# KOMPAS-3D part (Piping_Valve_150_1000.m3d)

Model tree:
1. Plane XY
2. Plane ZX
3. Plane ZY
4. X Axis
5. Y Axis
6. Z Axis
7. Origin
8. Sketch:1
9. Extrude:1  (labels: На расстояние 1; На расстояние 2)
     Толщина стенки 1 = 1; Толщина стенки 2 = 1; Расстояние 2 = 10
10. Sketch:5
11. Extrude:2  (labels: На расстояние 1; На расстояние 2)
     Толщина стенки 1 = 1; Толщина стенки 2 = 1; Угол 1 = 45; Расстояние 2 = 10
12. Sketch:7
13. Cut-Extrude:2  (labels: На расстояние 1)
     Толщина стенки 1 = 1; Толщина стенки 2 = 1; Расстояние 1 = 10; Расстояние 2 = 11
14. Intersection Axis of Two Planes:1
15. Circular Pattern:1  (labels: Экземпляр ( 1, 2 );; Вырезать элемент выдавливания:2; Экземпляр ( 1, 3 );; Вырезать элемент выдавливания:2)
16. Вырезать элемент выдавливания:2  (labels: Экземпляр ( 1, 6 );; Экземпляр ( 1, 7 );; Экземпляр ( 1, 8 );)
     N 1 = 1; Шаг 1 = 10; Шаг 2 = 360
17. Sketch:6
18. Cut-Extrude:1  (labels: На расстояние 1; На расстояние 2)
     Толщина стенки 1 = 1; Толщина стенки 2 = 1; Расстояние 1 = 11; Расстояние 2 = 3
19. Sketch:8
20. Attachment Point:1
21. Sketch:10
22. Parallel Plane:1
23. Sketch:12
24. Sketch:11
25. Revolve:1
     Толщина стенки 1 = 1; Толщина стенки 2 = 1; Угол 1 = 360; Угол 2 = 360
26. Mirror Body:2
27. Attachment Point:2
28. Sketch:13
29. Extrude:3  (labels: На расстояние 2)
     Толщина стенки 1 = 1; Толщина стенки 2 = 1; Расстояние 1 = 735; Расстояние 2 = 10
30. Sketch:15
31. Revolve:2
     Толщина стенки 1 = 1; Толщина стенки 2 = 1; Угол 1 = 360; Угол 2 = 360
32. Plane at Angle:1
     Угол = 45
33. Sketch:16
34. Extrude:4  (labels: На расстояние 2)
     Толщина стенки 1 = 1; Толщина стенки 2 = 1; Расстояние 1 = 1; Расстояние 2 = 10
35. Circular Pattern:2  (labels: Экземпляр ( 1, 2 );; Операция выдавливания:4; Экземпляр ( 1, 3 );; Операция выдавливания:4)
     N 1 = 1; Шаг 1 = 10; N 2 = 4; Шаг 2 = 360
36. Control point:1

Expressions: (Dm-Dn)*1.25; (Dn-d1)*0.5-1; Dm*0.5; D*0.075; Lz*0.4; D*0.05; D1z*1.3; Hmax*0.8
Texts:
  Valve Dn 150
  Three Point Plane
  Plane at Angle
  Line and Point Plane
  Axis through Two Vertices
  Axis of Feature
  Axis of Conical Surface
  Axis through Edge
  Приклеить элемент выдавливания
  Приклеить элемент вращения
  Приклеить кинематический элемент
  Приклеить элемент по сечениям
  Trim by Surface
  Trim by Sketch
  Feature with No History
  Intersection Axis of Two Planes
  Two Line Plane
  Line and Face Plane
  Bend by line
  Hole in sheet body
  Cut in sheet body
  Point in CM
  Linear Dimension from Line to Point
  Surface Finish Symbol
  Geometric Tolerance Symbol
  Текст на чертеже
  Линия-выноска #1
  Линия-выноска #2
  Линия-выноска #3
  Отклонения формы и база
  Марка координационной оси
  Марка/позиционное обозначение с линией-выноской
  Марка/позиционное обозначение на линии
  Марка/позиционное обозначение без линии-выноски
  Dm05
  Экземпляр ( 1, 2 );
  Экземпляр ( 1, 3 );
  Экземпляр ( 1, 4 );
  Экземпляр ( 1, 5 );
  Экземпляр ( 1, 6 );
  Экземпляр ( 1, 7 );
  Экземпляр ( 1, 8 );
